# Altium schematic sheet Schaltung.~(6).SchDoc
size A4
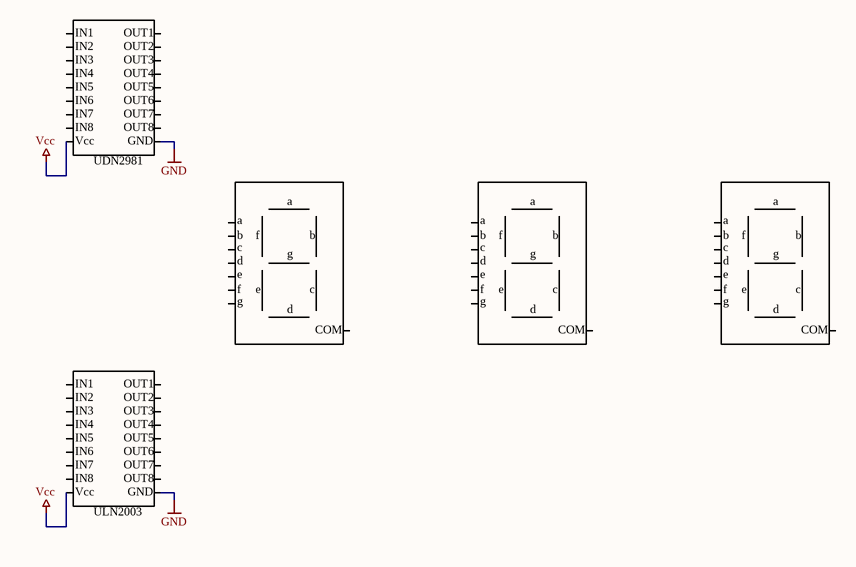
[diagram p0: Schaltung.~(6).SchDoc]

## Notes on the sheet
- IN1
- IN2
- IN3
- IN4
- IN5
- IN6
- OUT1
- OUT2
- OUT3
- OUT4
- OUT5
- OUT6
- IN7
- IN8
- Vcc
- UDN2981
- OUT7
- OUT8
- GND
- a
- b
- f
- c
- d
- e
- g
- COM
- ULN2003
